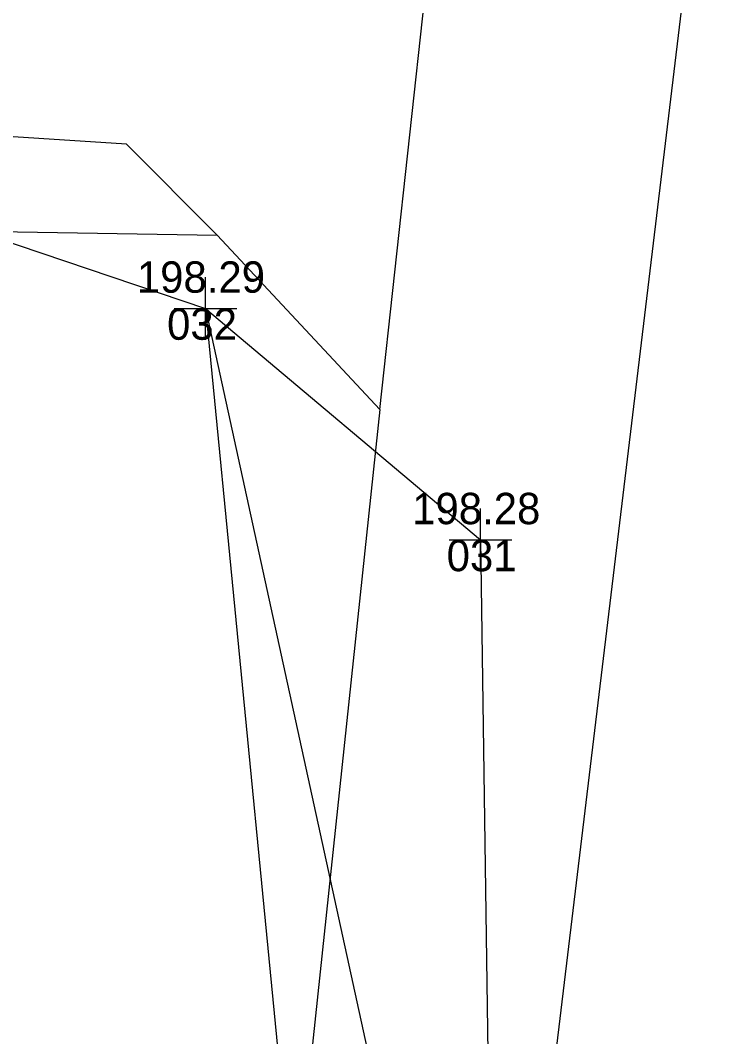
# Model space of a CAD drawing. Extents: x -706655 to -706193, y -1036183 to -1034979.
# Drawn here: x -706623.39 to -706612.36, y -1035124.1 to -1035107.9 of the extents above; entities that cross this region are included whole.
import ezdxf

# ---------------------------------------------------------------- set-up
doc = ezdxf.new("R2010")
doc.units = 0
for name, color, linetype in [('Hranice parcel', 7, 'Continuous'), ('křížky', 7, 'Continuous'), ('Stávající terén', 7, 'Continuous'), ('výšky', 7, 'Continuous'), ('čísla bodu', 7, 'Continuous')]:
    doc.layers.add(name, color=color, linetype=linetype)

msp = doc.modelspace()

# ---------------------------------------------------------------- linework, layer by layer
at = {"layer": 'Hranice parcel'}
for p, q in [((-706617.66, -1035114.1), (-706615.7, -1035096.22)), ((-706650.337, -1035110.851), (-706620.25, -1035111.32)), ((-706620.25, -1035111.32), (-706617.66, -1035114.1)), ((-706617.66, -1035114.1), (-706620.85, -1035144.24))]:
    msp.add_line(p, q, dxfattribs=at)
msp.add_lwpolyline([(-706620.25, -1035111.32), (-706621.7, -1035109.87), (-706632.56, -1035109.17), (-706644.89, -1035107.95), (-706648.091, -1035107.907)], dxfattribs=at)
at = {"layer": 'křížky'}
for p, q in [((-706620.44, -1035112.99), (-706620.44, -1035111.99)), ((-706620.94, -1035112.49), (-706619.94, -1035112.49)), ((-706620.44, -1035112.49), (-706620.44, -1035112.49)), ((-706616.05, -1035116.68), (-706616.05, -1035115.68)), ((-706616.55, -1035116.18), (-706615.55, -1035116.18)), ((-706616.05, -1035116.18), (-706616.05, -1035116.18))]:
    msp.add_line(p, q, dxfattribs=at)
at = {"layer": 'Stávající terén'}
for points in [[(-706608.917, -1035075.29), (-706610.31, -1035086.81), (-706611.88, -1035099.66), (-706615.39, -1035128.84), (-706617.25, -1035146.23)], [(-706630.18, -1035109.2), (-706620.44, -1035112.49), (-706618.86, -1035128.69), (-706620.88, -1035145.19)], [(-706620.44, -1035112.49), (-706616.88, -1035128.78), (-706618.96, -1035145.46)], [(-706620.44, -1035112.49), (-706616.05, -1035116.18), (-706615.87, -1035128.82), (-706617.82, -1035146.02)]]:
    msp.add_lwpolyline(points, dxfattribs=at)
at = {"layer": 'čísla bodu'}
for p, q in [((-706620.44, -1035112.99), (-706620.44, -1035111.99)), ((-706620.94, -1035112.49), (-706619.94, -1035112.49)), ((-706620.44, -1035112.49), (-706620.44, -1035112.49)), ((-706616.05, -1035116.68), (-706616.05, -1035115.68)), ((-706616.55, -1035116.18), (-706615.55, -1035116.18)), ((-706616.05, -1035116.18), (-706616.05, -1035116.18))]:
    msp.add_line(p, q, dxfattribs=at)

# ---------------------------------------------------------------- texts
at = {"layer": 'výšky'}
for s, p in [('198.29', (-706621.534, -1035112.24)), ('198.28', (-706617.142, -1035115.93))]:
    msp.add_text(s, height=0.5, dxfattribs=at).set_placement(p)
at = {"layer": 'čísla bodu'}
for s, p in [('032', (-706621.052, -1035112.99)), ('031', (-706616.592, -1035116.68))]:
    msp.add_text(s, height=0.5, dxfattribs=at).set_placement(p)

doc.saveas('drawing.dxf')
